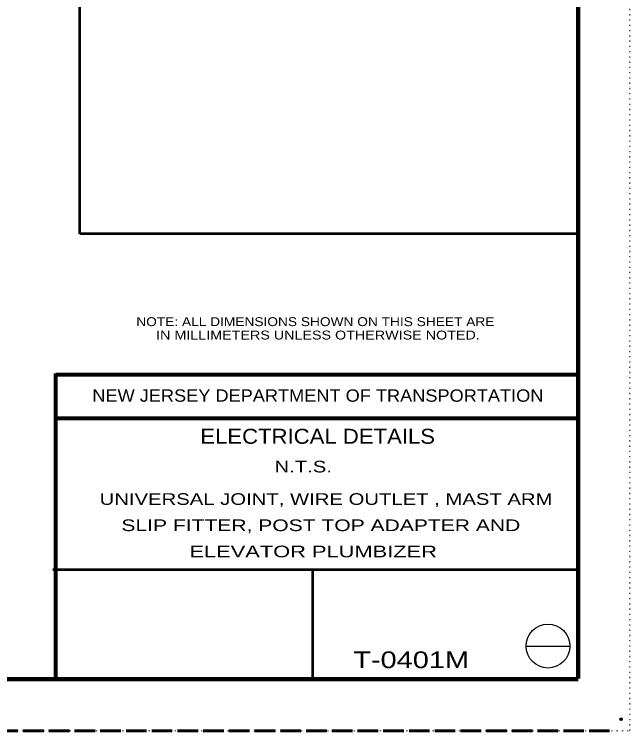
# Model space of a CAD drawing. Extents: x 312583 to 312854, y 144419 to 144597.
# Drawn here: x 312799.7 to 312853.5, y 144418.6 to 144481.2 of the extents above; entities that cross this region are included whole.
import ezdxf
from ezdxf.enums import TextEntityAlignment as Align

# ---------------------------------------------------------------- set-up
doc = ezdxf.new("R2010")
doc.units = 0
doc.header["$LTSCALE"] = 0.3
doc.header["$PDMODE"] = 32
doc.header["$PDSIZE"] = 0.15
doc.linetypes.add('DOTTED', pattern=[1.5, 0.3, -1.2])
doc.linetypes.add('LONG_DASHED', pattern=[7.5, 6, -1.5])
for name, color, linetype, lineweight in [('1', 7, 'Continuous', 40), ('10', 7, 'Continuous', 25), ('2', 7, 'Continuous', 13), ('62', 7, 'DOTTED', 13), ('63', 7, 'LONG_DASHED', 60)]:
    doc.layers.add(name, color=color, linetype=linetype, lineweight=lineweight)
doc.layers.add('5', color=7, linetype='Continuous')

msp = doc.modelspace()

# ---------------------------------------------------------------- linework, layer by layer
at = {"layer": '1', "lineweight": 53}
for p, q in [((312805.4109, 144462.0318), (312805.4109, 144585.0846)), ((312849, 144462.0318), (312805.4109, 144462.0318)), ((312849, 144432.6666), (312803.0383, 144432.6666)), ((312825.7547, 144432.6666), (312825.7547, 144423.1446))]:
    msp.add_line(p, q, dxfattribs=at)
at = {"layer": '1', "lineweight": 158}
for p, q in [((312849, 144423.1446), (312849, 144585.0846)), ((312616.5, 144423.0846), (312849, 144423.0846))]:
    msp.add_line(p, q, dxfattribs=at)
at = {"layer": '1', "lineweight": 80}
for p, q in [((312803.31, 144423.1446), (312803.31, 144449.8146)), ((312803.31, 144449.7246), (312849, 144449.7246)), ((312803.31, 144445.9146), (312849, 144445.9146))]:
    msp.add_line(p, q, dxfattribs=at)
at = {"layer": '1'}
msp.add_point((312852.75, 144419.5846), dxfattribs=at)
at = {"layer": '10'}
msp.add_line((312844.4384, 144425.9659), (312848.2794, 144425.9659), dxfattribs=at)
msp.add_circle((312846.3494, 144425.9805), 1.9159, dxfattribs=at)
at = {"layer": '62'}
msp.add_lwpolyline([(312601.2, 144418.5846), (312853.5, 144418.5846), (312853.5, 144596.7846)], dxfattribs=at)
at = {"layer": '63'}
msp.add_line((312851.75, 144418.5846), (312583.526, 144418.5846), dxfattribs=at)

# ---------------------------------------------------------------- texts
at = {"layer": '1'}
for s, width, p in [('NOTE: ALL DIMENSIONS SHOWN ON THIS SHEET ARE', 1.15, (312810.3449, 144453.9679)), ('     IN MILLIMETERS UNLESS OTHERWISE NOTED.', 1.2, (312810.3448, 144452.7979))]:
    msp.add_text(s, height=0.78, dxfattribs=dict(at, width=width)).set_placement(p)
at = {"layer": '1', "width": 1.1}
for s, height, p in [('NEW JERSEY DEPARTMENT OF TRANSPORTATION', 1.08, (312826.2285, 144447.3546)), ('ELECTRICAL DETAILS', 1.315, (312826.2109, 144443.6759))]:
    msp.add_text(s, height=height, dxfattribs=at).set_placement(p, align=Align.CENTER)
at = {"layer": '2'}
for s, width, p in [('     N.T.S. ', 1.3, (312823.9633, 144441.1717)), ('   UNIVERSAL JOINT, WIRE OUTLET , MAST ARM  ', 1.3, (312826.6976, 144438.3322)), ('      SLIP FITTER, POST TOP ADAPTER AND     ', 1.35, (312826.2339, 144436.0399)), ('             ELEVATOR PLUMBIZER             ', 1.4, (312825.8198, 144433.7476))]:
    msp.add_text(s, height=1.02, dxfattribs=dict(at, width=width)).set_placement(p, align=Align.CENTER)
at = {"layer": '5', "width": 1.3}
msp.add_text('T-0401M  ', height=1.457, dxfattribs=at).set_placement((312835.0922, 144424.0569), align=Align.CENTER)

doc.saveas('drawing.dxf')
